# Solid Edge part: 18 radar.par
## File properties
Author: Henri
Template: Normal.par
Last saved by: Henri
Revision: 2
Application: Solid Edge
Accuracy: 0,990
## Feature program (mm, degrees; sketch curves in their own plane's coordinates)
lofted protrusion "LoftedProtrusion_2"  StartTangentMagnitude1 = 1; EndTangentMagnitude1 = 1
sketch for "unnamed RevolvedProtrusion 1" plane through (0, 0, 0) normal (0, -1, 0) x-axis (1, 0, 0)
  arc centre (13.7942, 37.4562) radius 18.0371 from (-4.0445, 40.1239) to (0.0395, 25.7882) ccw
  arc centre (13.8273, 18.1223) radius 15.7756 from (0.0395, 25.7882) to (4.93, 31.1495) cw
  arc centre (5.2788, 31.0582) radius 0.3606 from (4.93, 31.1495) to (4.938, 30.9405) ccw
  arc centre (5.0798, 30.9895) radius 0.15 from (4.938, 30.9405) to (5.1226, 30.8457) ccw
  arc centre (5.1654, 30.7019) radius 0.15 from (5.1226, 30.8457) to (5.2714, 30.808) cw
  line (5.5189, 30.5605) -> (5.2714, 30.808)
  line (5.5189, 30.5605) -> (0.0149, 25.0565)
  arc centre (13.7942, 37.4562) radius 18.5371 from (-4.4811, 40.5605) to (0.0149, 25.0565) ccw
  line (-4.0445, 40.1239) -> (-4.4811, 40.5605)
revolve "unnamed RevolvedProtrusion 1" add finite 360 deg
sketch for "unnamed Protrusion 1" plane through (0, 0, 15) normal (0, 0, 1) x-axis (0, 1, 0)
  circle centre (0, 0) radius 0.75
extrude "unnamed Protrusion 1" add through along +normal
sketch for "unnamed RevolvedProtrusion 2" plane through (0, 0, 0) normal (0, -1, 0) x-axis (1, 0, 0)
  line (0, 15) -> (0, 21.8615)
  line (0, 21.8615) -> (1.7626, 20.7727)
  line (1.7626, 20.7727) -> (1.7626, 17.9359)
  line (1.7626, 17.9359) -> (3.5964, 15)
  line (3.5964, 15) -> (0, 15)
revolve "unnamed RevolvedProtrusion 2" add finite 360 deg
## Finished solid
Body 1: solid body, 18 faces, 24 edges, 8 vertices.
  Faces by surface: torus 6, plane 4, spline 4, cone 2, cylinder 2
  Edges by curve: circle 11, line 8, spline 4, intersection 1
Bounding box of the edges (mm; curved faces can reach further): 30.969 x 30.901 x 40.560, from (-15.4503, -15.4503, 0) to (15.5189, 15.4503, 40.5605).
Cylindrical faces by radius (mm): R0.75 x1, R1.7626 x1
Conical faces (half-angle, radius in mm at the cone's reference point): 31.9903 deg R1.7626 x1, 58.2935 deg R0 x1
Toroidal faces (ring radius, tube radius in mm): R-14.6701 r15.7756 x1, R-0.9755 r18.0371 x1, R-0.9755 r18.5371 x1, R0.35 r0.15 x1, R0.5217 r0.3606 x1, R0.6139 r0.15 x1
Planar faces by outward normal: +z 1, -z 1, oblique 2
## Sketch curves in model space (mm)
line (1.7626, 0, 20.7727) -> (1.7626, 0, 17.9359)
line (1.7626, 0, 17.9359) -> (3.5964, 0, 15)
line (3.5964, 0, 15) -> (0, 0, 15)
line (0, 0, 15) -> (0, 0, 21.8615)
line (0, 0, 21.8615) -> (1.7626, 0, 20.7727)
circle centre (0, 0, 15) radius 0.75
circle centre (0, 0, 15) radius 0.75
arc centre (13.7942, 0, 37.4562) radius 18.5371 from (-4.4811, 0, 40.5605) through (-4.0094, 0, 32.2934) to (0.0149, 0, 25.0565)
line (-4.0445, 0, 40.1239) -> (-4.4811, 0, 40.5605)
arc centre (13.7942, 0, 37.4562) radius 18.0371 from (-4.0445, 0, 40.1239) through (-3.5527, 0, 32.5144) to (0.0395, 0, 25.7882)
arc centre (13.8273, 0, 18.1223) radius 15.7756 from (0.0395, 0, 25.7882) through (2.1723, 0, 28.7538) to (4.93, 0, 31.1495)
arc centre (5.2788, 0, 31.0582) radius 0.3606 from (4.93, 0, 31.1495) through (4.9185, 0, 31.0444) to (4.938, 0, 30.9405)
arc centre (5.0798, 0, 30.9895) radius 0.15 from (4.938, 0, 30.9405) through (5.0112, 0, 30.856) to (5.1226, 0, 30.8457)
arc centre (5.1654, 0, 30.7019) radius 0.15 from (5.1226, 0, 30.8457) through (5.2022, 0, 30.8473) to (5.2714, 0, 30.808)
line (5.5189, 0, 30.5605) -> (5.2714, 0, 30.808)
line (5.5189, 0, 30.5605) -> (0.0149, 0, 25.0565)
line (-15, 15, 10) -> (15, 15, 10)
line (15, 15, 10) -> (15, -15, 10)
line (15, -15, 10) -> (-15, -15, 10)
line (-15, -15, 10) -> (-15, 15, 10)
line (-10, 10, 15) -> (10, 10, 15)
line (10, 10, 15) -> (10, -10, 15)
line (10, -10, 15) -> (-10, -10, 15)
line (-10, -10, 15) -> (-10, 10, 15)
line (15, 15, 5) -> (15, -15, 5)
line (15, -15, 5) -> (-15, -15, 5)
line (-15, -15, 5) -> (-15, 15, 5)
line (-15, 15, 5) -> (15, 15, 5)
line (10, 10, 0) -> (10, -10, 0)
line (10, -10, 0) -> (-10, -10, 0)
line (-10, -10, 0) -> (-10, 10, 0)
line (-10, 10, 0) -> (10, 10, 0)
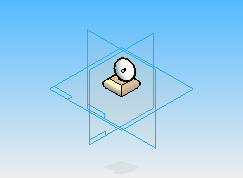
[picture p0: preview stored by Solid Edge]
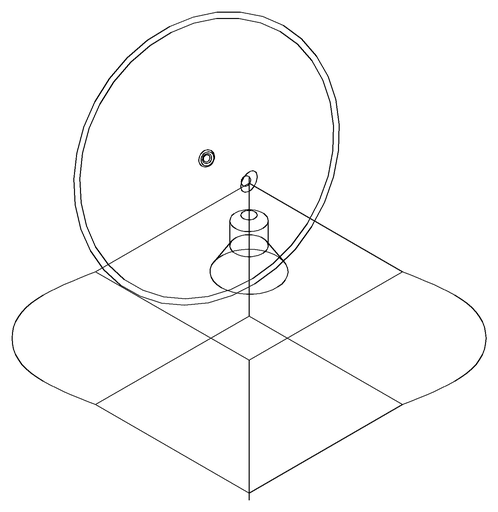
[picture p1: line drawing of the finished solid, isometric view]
